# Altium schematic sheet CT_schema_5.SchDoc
size 422 x 246 mm
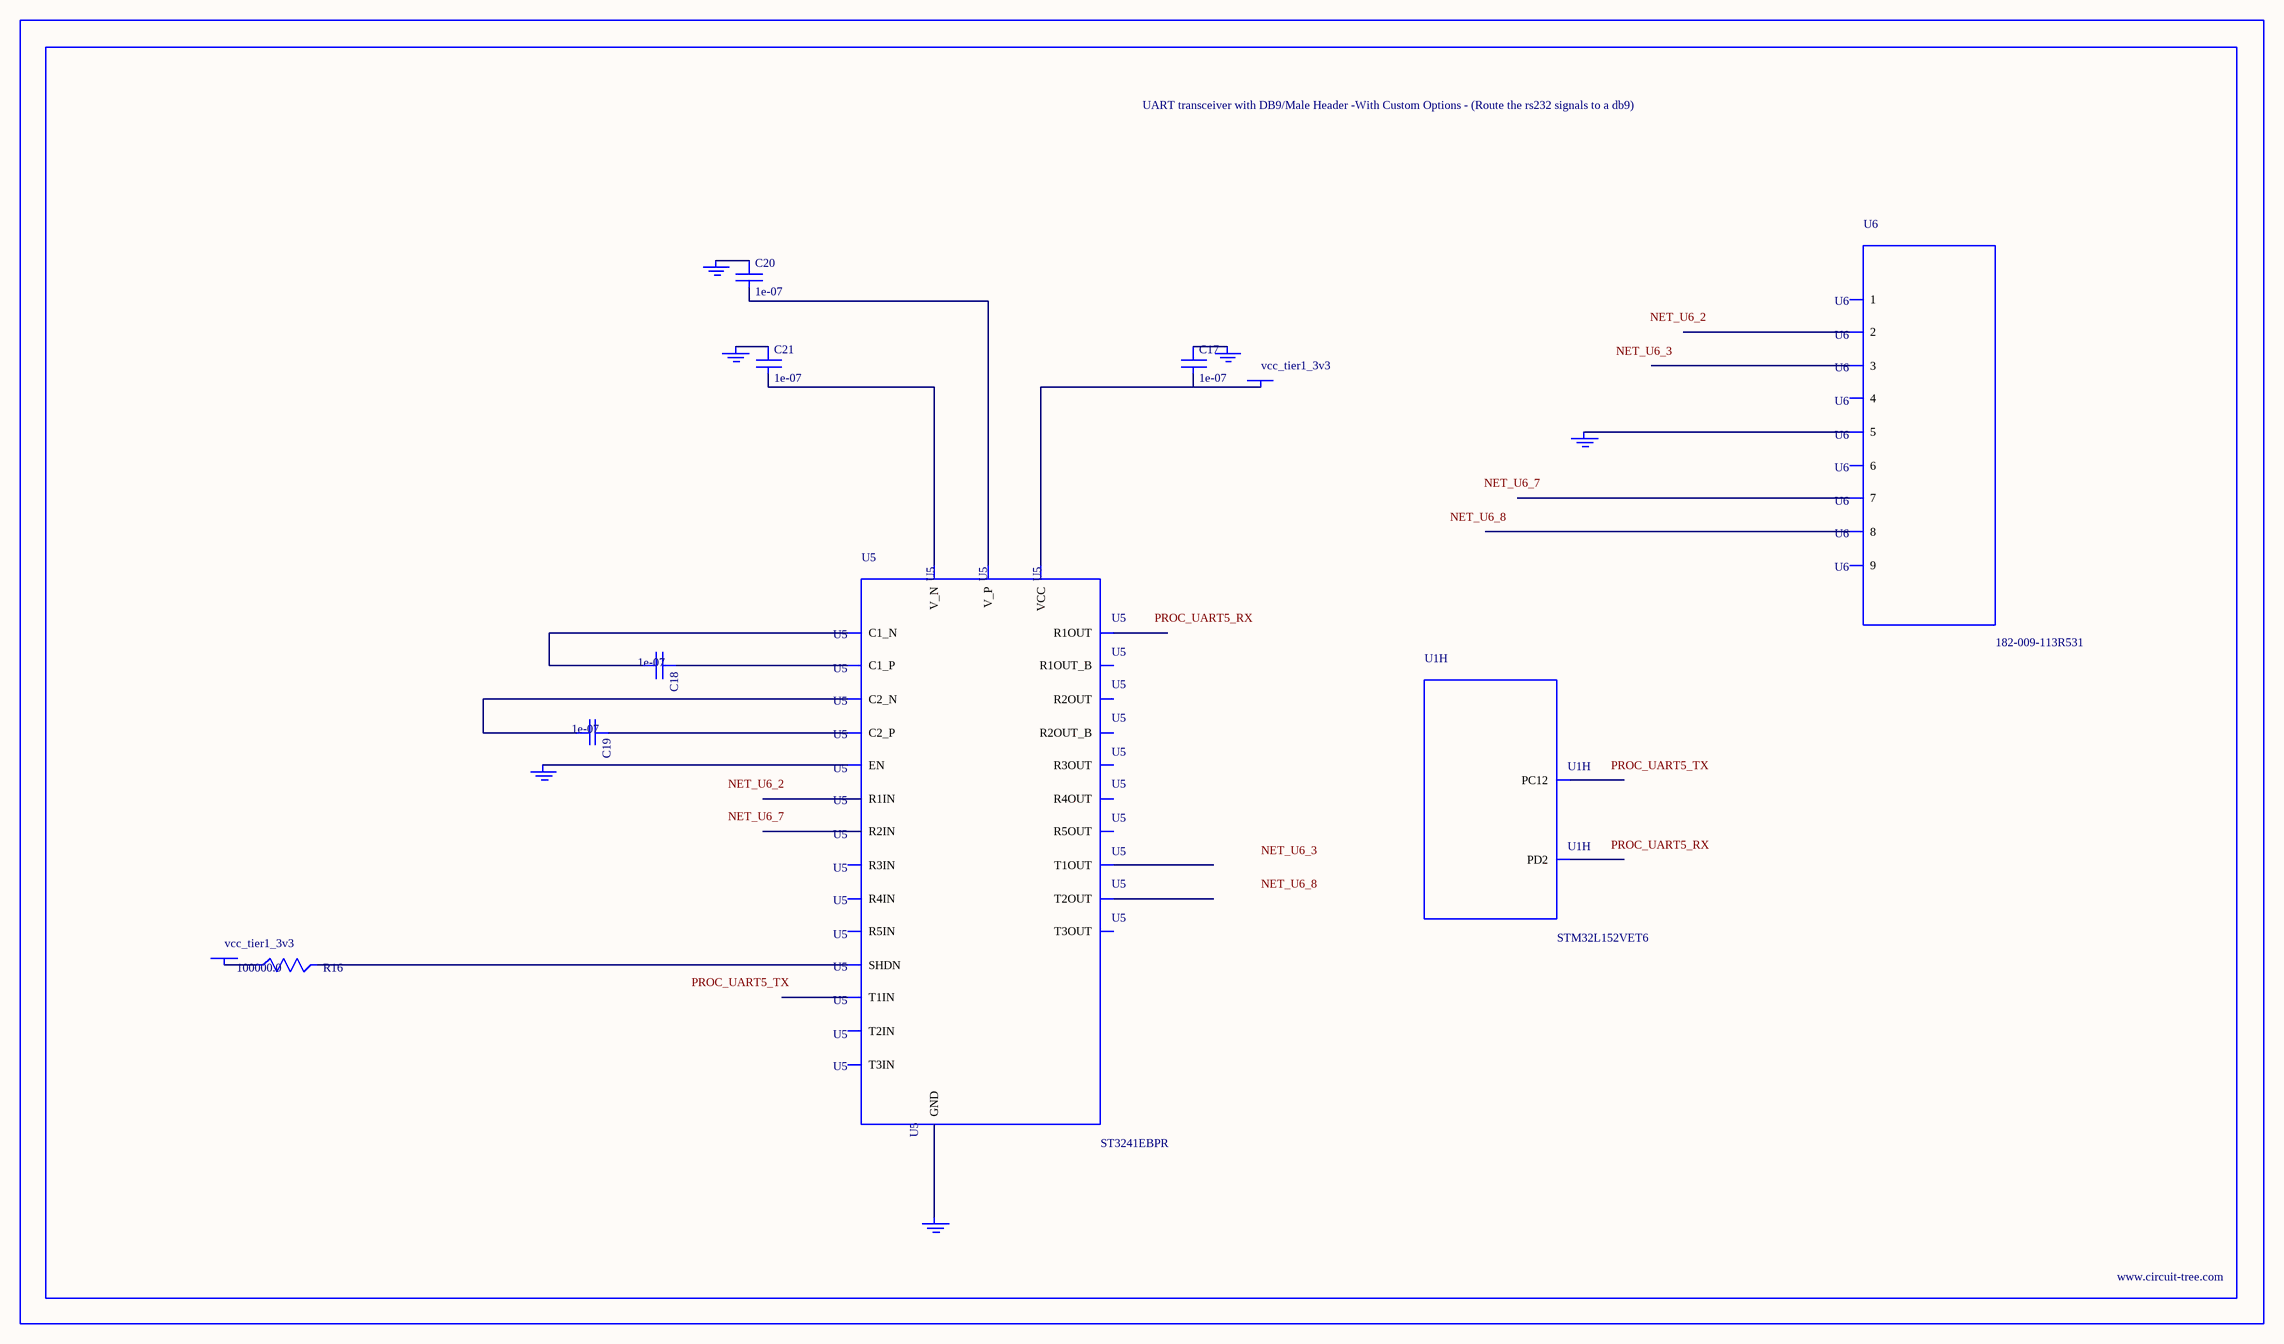
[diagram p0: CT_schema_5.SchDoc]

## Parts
BORDER4  (no value)
C17  1e-07  [C0402]
C18  1e-07  [C0402]
C19  1e-07  [C0402]
C20  1e-07  [C0402]
C21  1e-07  [C0402]
GND_INSTANCE_4_0  (no value)
GND_INSTANCE_4_1  (no value)
GND_INSTANCE_4_2  (no value)
GND_INSTANCE_4_3  (no value)
GND_INSTANCE_4_4  (no value)
GND_INSTANCE_4_5  (no value)
POWER_INSTANCE_4_0  vcc_tier1_3v3
POWER_INSTANCE_4_1  vcc_tier1_3v3
R16  100000.0  [R0603]
U1  STM32L152VET6  [LQFP100]  (part H of 10)
U5  ST3241EBPR  [SSOP-28]
U6  182-009-113R531  [182-009-MALE]

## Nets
NetC17_1: C17.1 GND_INSTANCE_4_2.0(GND)
NetC17_2: C17.2 POWER_INSTANCE_4_1.0(PWR) U5.26(VCC)
NetC18_1: C18.1 U5.28(C1_P)
NetC18_2: C18.2 U5.24(C1_N)
NetC19_1: C19.1 U5.1(C2_P)
NetC19_2: C19.2 U5.2(C2_N)
NetC20_1: C20.1 GND_INSTANCE_4_3.0(GND)
NetC20_2: C20.2 U5.27(V_P)
NetC21_1: C21.1 GND_INSTANCE_4_0.0(GND)
NetC21_2: C21.2 U5.3(V_N)
NetGND_INSTANCE_4_1_0: GND_INSTANCE_4_1.0(GND) U5.23(EN)
NetGND_INSTANCE_4_4_0: GND_INSTANCE_4_4.0(GND) U5.25(GND)
NetGND_INSTANCE_4_5_0: GND_INSTANCE_4_5.0(GND) U6.5
NetPOWER_INSTANCE_4_0_0: POWER_INSTANCE_4_0.0(PWR) R16.1
NetR16_2: R16.2 U5.22(SHDN)

Not connected (* = marked no-connect by the designer): U1 80(PC12) 83(PD2); U5 4(R1IN) 5(R2IN) 6(R3IN) 7(R4IN) 8(R5IN) 9(T1OUT) 10(T2OUT) 11(T3OUT) 12(T3IN) 13(T2IN) 14(T1IN) 15(R5OUT) 16(R4OUT) 17(R3OUT) 18(R2OUT) 19(R1OUT) 20(R2OUT_B) 21(R1OUT_B); U6 1 2 3 4 6 7 8 9

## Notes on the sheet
- Labels drawn without touching a wire or pin: NET_U6_2, NET_U6_3, NET_U6_7, NET_U6_8, PROC_UART5_RX, PROC_UART5_TX

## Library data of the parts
BORDER4 = BORDER_PAGE4
C17-C21 = C0402C104K3RACTU
GND_INSTANCE_4_0-GND_INSTANCE_4_5 = GND
POWER_INSTANCE_4_0 POWER_INSTANCE_4_1 = PWR
R16 = RC0603JR-07100KL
